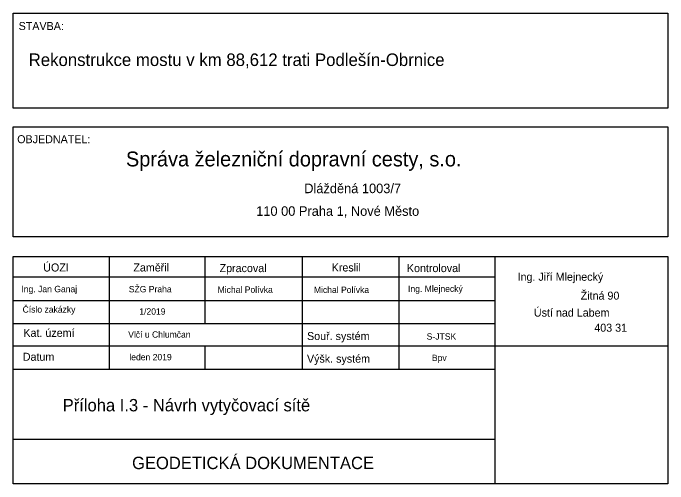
# Model space of a CAD drawing. Extents: x -879530 to -879371, y -1019242 to -1019127.
import ezdxf

# ---------------------------------------------------------------- set-up
doc = ezdxf.new("R2010")
doc.units = 0
doc.layers.add('LEGENDA', color=7, linetype='Continuous')
doc.layers.add('tabulka', color=7, linetype='Continuous')

msp = doc.modelspace()

# ---------------------------------------------------------------- linework, layer by layer
at = {"layer": 'tabulka'}
for p, q in [((-879530.09, -1019186.45), (-879371.44, -1019186.45)), ((-879506.8, -1019186.45), (-879506.8, -1019213.77)), ((-879483.66, -1019186.45), (-879483.66, -1019202.65)), ((-879460.06, -1019186.45), (-879460.06, -1019213.77)), ((-879436.61, -1019186.45), (-879436.61, -1019213.77)), ((-879413.31, -1019241.58), (-879413.31, -1019186.45)), ((-879530.09, -1019191.36), (-879413.31, -1019191.36)), ((-879530.09, -1019197.07), (-879413.31, -1019197.07)), ((-879530.09, -1019202.65), (-879413.31, -1019202.65)), ((-879530.09, -1019208.07), (-879371.44, -1019208.07)), ((-879483.66, -1019208.07), (-879483.66, -1019213.77)), ((-879530.09, -1019213.77), (-879413.31, -1019213.77)), ((-879530.09, -1019230.76), (-879413.31, -1019230.76))]:
    msp.add_line(p, q, dxfattribs=at)
for points in [[(-879530.09, -1019127.36), (-879371.44, -1019127.36), (-879371.44, -1019150.43), (-879530.09, -1019150.43)], [(-879530.09, -1019154.95), (-879371.44, -1019154.95), (-879371.44, -1019181.64), (-879530.09, -1019181.64)]]:
    msp.add_lwpolyline(points, close=True, dxfattribs=at)
msp.add_lwpolyline([(-879371.44, -1019186.45), (-879371.44, -1019241.58), (-879530.09, -1019241.58), (-879530.09, -1019186.45)], dxfattribs=at)

# ---------------------------------------------------------------- texts
at = {"layer": 'LEGENDA'}
msp.add_text('Rekonstrukce mostu v km 88,612 trati Podlešín-Obrnice', height=3.04, dxfattribs=at).set_placement((-879526.32, -1019140.2))
at = {"layer": 'tabulka'}
for s, height, p in [('STAVBA:', 1.94, (-879528.75, -1019131.47)), ('OBJEDNATEL:', 1.94, (-879529.1, -1019158.93)), ('Správa železniční dopravní cesty, s.o.', 3.61, (-879502.75, -1019164.56)), ('Dlážděná 1003/7', 2.32, (-879459.55, -1019171.05)), ('110 00 Praha 1, Nové Město', 2.32, (-879471.19, -1019176.55)), ('ÚOZI', 1.94, (-879522.79, -1019190.05)), ('Zaměřil', 1.94, (-879500.95, -1019190.05)), ('Zpracoval', 1.94, (-879480.06, -1019190.2)), ('Kreslil', 1.94, (-879452.9, -1019190.05)), ('Kontroloval', 1.94, (-879434.68, -1019190.2)), ('Ing. Jiří Mlejnecký', 1.94, (-879407.86, -1019192.3)), ('Ing. Jan Ganaj', 1.552, (-879528.08, -1019195.08)), ('SŽG Praha', 1.552, (-879502.06, -1019195.11)), ('Ing. Mlejnecký', 1.552, (-879434.4, -1019195)), ('Michal Polívka', 1.552, (-879480.54, -1019195.23)), ('Michal Polívka', 1.552, (-879457.21, -1019195.27)), ('Žitná 90', 1.94, (-879392.57, -1019196.88)), ('Číslo zakázky', 1.552, (-879527.79, -1019200.03)), ('1/2019', 1.552, (-879499.51, -1019200.52)), ('Ústí nad Labem', 1.94, (-879403.9, -1019201)), ('403 31', 1.94, (-879389.27, -1019204.66)), ('Kat. území', 1.94, (-879527.6, -1019205.91)), ('Vlčí u Chlumčan', 1.552, (-879502.2, -1019206.11)), ('Souř. systém', 1.94, (-879458.87, -1019206.68)), ('S-JTSK', 1.552, (-879429.88, -1019206.59)), ('Datum', 1.94, (-879527.74, -1019211.71)), ('leden 2019', 1.552, (-879501.93, -1019211.6)), ('Výšk. systém', 1.94, (-879458.89, -1019212.17)), ('Bpv', 1.552, (-879428.62, -1019211.78)), ('Příloha I.3 - Návrh vytyčovací sítě', 3, (-879518.08, -1019223.98)), ('GEODETICKÁ DOKUMENTACE ', 3, (-879501.27, -1019237.99))]:
    msp.add_text(s, height=height, dxfattribs=at).set_placement(p)

doc.saveas('drawing.dxf')
